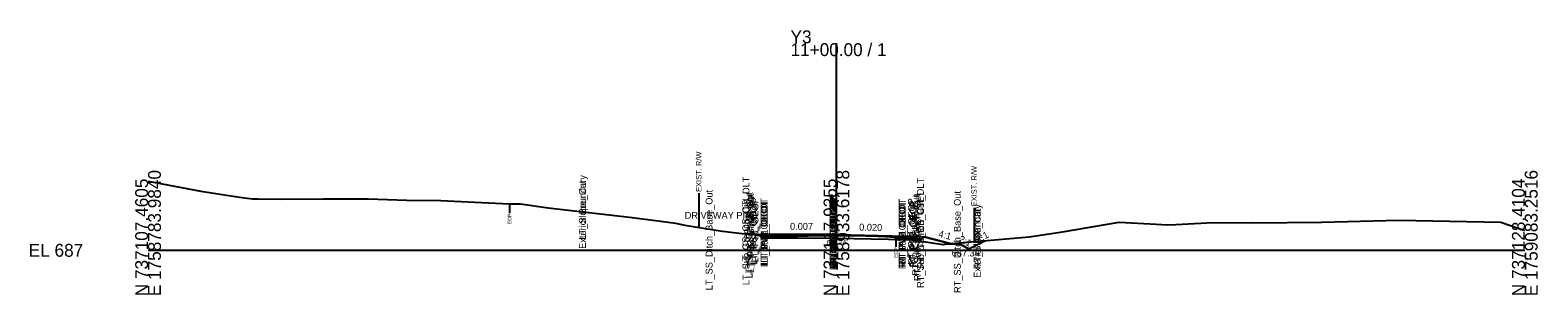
# Model space of a CAD drawing. Extents: x -26 to 1760432, y -10 to 737112.
# Drawn here: x -25.7 to 302.8, y 990.3 to 1047.9 of the extents above; entities that cross this region are included whole.
import ezdxf

# ---------------------------------------------------------------- set-up
doc = ezdxf.new("R2010")
doc.units = 0
for name, color, linetype in [('Default', 7, 'Continuous'), ('Exist Cross Section Cell', 7, 'Continuous'), ('Exist XS Center Line Elevation Label', 7, 'Continuous'), ('Exist XS Ground Line', 7, 'Continuous'), ('Old_Level_1', 7, 'Continuous'), ('Old_Level_10', 7, 'Continuous'), ('Prop CMT Pvmt Course 1', 7, 'Continuous'), ('Prop CMT Pvmt Course 2', 7, 'Continuous'), ('Prop CMT Pvmt Course 3', 7, 'Continuous'), ('Prop CMT Pvmt Surface', 7, 'Continuous'), ('Prop CMT Pvmt Surface Shoulder', 7, 'Continuous'), ('Prop CMT Pvmt Wedge Surface 1', 7, 'Continuous'), ('Prop CMT Shld Paved Course 1', 7, 'Continuous'), ('Prop CMT Shld Paved Course 2', 7, 'Continuous'), ('Prop CMT Shld Paved Course 3', 7, 'Continuous'), ('Prop CMT Slope Grass', 7, 'Continuous'), ('Prop CMT Subgrade Earthwork', 7, 'Continuous'), ('Prop XS DDE', 7, 'Continuous'), ('Prop XS Ditch Standard Text', 7, 'Continuous'), ('Prop XS Earthwork Shape', 7, 'Continuous'), ('Prop XS SE Text', 7, 'Continuous'), ('Prop XS Side Slope Text', 7, 'Continuous'), ('Scratch_Level_5', 7, 'Continuous'), ('Scratch_Level_7', 7, 'Continuous')]:
    doc.layers.add(name, color=color, linetype=linetype)

msp = doc.modelspace()

# ---------------------------------------------------------------- linework, layer by layer
at = {"layer": 'Exist Cross Section Cell'}
for p, q in [((150, 1000), (150, 1045.08)), ((0, 1000), (150, 1000)), ((150, 1000), (300, 1000))]:
    msp.add_line(p, q, dxfattribs=at)
at = {"layer": 'Exist XS Ground Line'}
msp.add_lwpolyline([(0, 1015.03), (11.53, 1012.84), (19.94, 1011.56), (22.79, 1011.22), (23.98, 1011.17), (29.02, 1011.13), (38.07, 1011.2), (40.86, 1011.2), (48.06, 1011.19), (56.28, 1010.93), (63.82, 1010.82), (66.7, 1010.69), (78.78, 1010.12), (81.18, 1010.12), (87.19, 1009.22), (96.07, 1008.24), (104.93, 1007.18), (111.18, 1006.39), (114.96, 1005.88), (116.94, 1005.49), (125.12, 1004.2), (125.86, 1004.11), (127.58, 1003.9), (130.08, 1003.59), (132.15, 1003.41), (132.59, 1003.37), (134.49, 1003.14), (135.1, 1003.08), (135.48, 1003.05), (136.03, 1003.02), (136.64, 1002.98), (136.95, 1002.99), (137.29, 1003.02), (137.6, 1003.03), (139.18, 1003.06), (140.11, 1003.07), (141.52, 1003.1), (142.61, 1003.12), (143.86, 1003.16), (145.12, 1003.2), (146.2, 1003.2), (147.63, 1003.21), (149.84, 1003.24), (152.64, 1003.21), (153.23, 1003.21), (155.14, 1003.2), (155.57, 1003.19), (157.91, 1003.15), (160.16, 1003.06), (160.72, 1003.01), (162.83, 1002.83), (173.27, 1001.28), (173.59, 1001.31), (191.99, 1002.92), (199.23, 1004.02), (211.62, 1006.09), (219.68, 1005.69), (222.07, 1005.56), (223.97, 1005.63), (232.09, 1006.03), (240.75, 1005.96), (255.74, 1006.11), (272.58, 1006.53), (294.8, 1006.1), (300, 1004.3)], dxfattribs=at)
at = {"layer": 'Old_Level_10'}
for p, q in [((120, 1012.41), (120, 1005.01)), ((78.78, 1010.12), (78.78, 1008.07)), ((180, 1009.27), (180, 1001.87)), ((162.94, 1002.81), (162.94, 1000.76))]:
    msp.add_line(p, q, dxfattribs=at)
at = {"layer": 'Prop CMT Pvmt Course 1'}
for points in [[(150, 1003.41), (135, 1003.51)], [(135, 1003.51), (135, 1003.26)], [(135, 1003.26), (150, 1003.16)], [(150, 1003.16), (150, 1003.41)], [(150, 1003.41), (165.09, 1003.11)], [(165.09, 1002.86), (162.94, 1002.9)], [(165.09, 1003.11), (165.09, 1002.86)]]:
    msp.add_lwpolyline(points, dxfattribs=at)
msp.add_lwpolyline([(150, 1003.16), (150, 1003.29), (150, 1003.29), (150, 1003.16)], close=True, dxfattribs=at)
at = {"layer": 'Prop CMT Pvmt Course 2'}
msp.add_line((137.6, 1003.04), (137.6, 1003.25), dxfattribs=at)
for points in [[(150, 1003.16), (135, 1003.26)], [(135, 1003.26), (135, 1003.05)], [(135, 1003.05), (137.6, 1003.04)], [(162.94, 1002.9), (165.09, 1002.86)], [(165.09, 1002.65), (162.94, 1002.7)], [(165.09, 1002.86), (165.09, 1002.65)]]:
    msp.add_lwpolyline(points, dxfattribs=at)
at = {"layer": 'Prop CMT Pvmt Course 3'}
msp.add_line((137.6, 1003.03), (137.6, 1003.04), dxfattribs=at)
for points in [[(137.6, 1003.04), (135, 1003.05)], [(135, 1003.05), (135, 1002.72)], [(135, 1002.72), (137.6, 1002.7)], [(162.94, 1002.7), (165.09, 1002.65)], [(165.09, 1002.32), (162.94, 1002.36)], [(165.09, 1002.65), (165.09, 1002.32)]]:
    msp.add_lwpolyline(points, dxfattribs=at)
at = {"layer": 'Prop CMT Pvmt Surface'}
for points in [[(150, 1003.41), (135, 1003.51)], [(150, 1003.41), (165.09, 1003.11)]]:
    msp.add_lwpolyline(points, dxfattribs=at)
at = {"layer": 'Prop CMT Pvmt Surface Shoulder'}
msp.add_lwpolyline([(165.09, 1003.11), (167.09, 1003.07)], dxfattribs=at)
at = {"layer": 'Prop CMT Pvmt Wedge Surface 1'}
for p, q in [((137.6, 1003.25), (137.6, 1003.37)), ((150, 1003.29), (137.6, 1003.37)), ((137.6, 1003.37), (137.6, 1003.25)), ((137.6, 1003.25), (144.92, 1003.2)), ((137.6, 1003.25), (137.6, 1003.04)), ((144.92, 1003.2), (137.6, 1003.25)), ((137.6, 1003.04), (137.6, 1003.03)), ((150, 1003.24), (150, 1003.29)), ((150, 1003.29), (150, 1003.24)), ((154.38, 1003.2), (150, 1003.29)), ((162.94, 1003.03), (158.99, 1003.11)), ((162.94, 1002.81), (162.94, 1003.03))]:
    msp.add_line(p, q, dxfattribs=at)
for points in [[(150, 1003.29), (137.6, 1003.37)], [(137.6, 1003.03), (139.18, 1003.06), (140.11, 1003.07), (141.52, 1003.1), (142.61, 1003.12), (143.86, 1003.16), (144.92, 1003.2)], [(144.92, 1003.2), (145.12, 1003.2), (146.2, 1003.2), (147.63, 1003.21), (149.84, 1003.24), (150, 1003.24)], [(150, 1003.29), (162.94, 1003.03)], [(150, 1003.24), (152.64, 1003.21), (153.23, 1003.21), (154.38, 1003.2)], [(158.99, 1003.11), (160.16, 1003.06), (160.72, 1003.01), (162.83, 1002.83), (162.94, 1002.81)], [(162.94, 1002.81), (162.94, 1002.9), (162.94, 1003.03)]]:
    msp.add_lwpolyline(points, dxfattribs=at)
at = {"layer": 'Prop CMT Shld Paved Course 1'}
for points in [[(135, 1003.51), (134.75, 1003.26)], [(134.75, 1003.26), (135, 1003.26)], [(135, 1003.26), (135, 1003.51)], [(165.09, 1003.11), (167.09, 1003.07), (167.34, 1002.82)], [(165.09, 1002.86), (165.09, 1003.11)], [(167.34, 1002.82), (165.09, 1002.86)]]:
    msp.add_lwpolyline(points, dxfattribs=at)
at = {"layer": 'Prop CMT Shld Paved Course 2'}
for points in [[(135, 1003.26), (134.75, 1003.26), (134.54, 1003.06)], [(134.54, 1003.06), (137, 1003.04)], [(135, 1003.05), (135, 1003.26)], [(165.09, 1002.86), (167.34, 1002.82), (167.55, 1002.6)], [(165.09, 1002.65), (165.09, 1002.86)], [(167.55, 1002.6), (165.09, 1002.65)]]:
    msp.add_lwpolyline(points, dxfattribs=at)
at = {"layer": 'Prop CMT Shld Paved Course 3'}
for points in [[(135, 1003.05), (134.54, 1003.06), (134.04, 1003.06), (133.71, 1002.73)], [(133.71, 1002.73), (135, 1002.72)], [(135, 1002.72), (135, 1003.05)], [(165.09, 1002.65), (167.55, 1002.6), (168.05, 1002.59), (168.39, 1002.25)], [(165.09, 1002.32), (165.09, 1002.65)], [(168.39, 1002.25), (165.09, 1002.32)]]:
    msp.add_lwpolyline(points, dxfattribs=at)
at = {"layer": 'Prop CMT Slope Grass'}
for points in [[(135, 1003.51), (132.48, 1003.38)], [(167.09, 1003.07), (169.09, 1002.91), (175, 1001.43)]]:
    msp.add_lwpolyline(points, dxfattribs=at)
at = {"layer": 'Prop CMT Subgrade Earthwork'}
for p, q in [((137.6, 1003.03), (137.6, 1002.7)), ((162.94, 1002.36), (162.94, 1002.81))]:
    msp.add_line(p, q, dxfattribs=at)
for points in [[(133.71, 1002.73), (133.04, 1003.41)], [(135, 1002.72), (133.71, 1002.73)], [(137.6, 1002.7), (135, 1002.72)], [(162.94, 1002.36), (165.09, 1002.32)], [(165.09, 1002.32), (168.39, 1002.25)], [(168.39, 1002.25), (169.05, 1002.91)]]:
    msp.add_lwpolyline(points, dxfattribs=at)
at = {"layer": 'Prop XS DDE'}
for p, q in [((178.86, 1000.34), (182.33, 1002.07)), ((177, 1001.27), (175, 1001.43)), ((178.86, 1000.34), (177, 1001.27))]:
    msp.add_line(p, q, dxfattribs=at)
at = {"layer": 'Prop XS Earthwork Shape'}
for points in [[(133.14, 1003.3), (133.04, 1003.41), (132.48, 1003.38), (132.59, 1003.37)], [(165.09, 1002.32), (166.47, 1002.29), (162.83, 1002.83), (160.72, 1003.01), (160.16, 1003.06), (157.91, 1003.15), (155.57, 1003.19), (155.14, 1003.2), (153.23, 1003.21), (152.64, 1003.21), (149.84, 1003.24), (147.63, 1003.21), (146.2, 1003.2), (145.12, 1003.2), (143.86, 1003.16), (142.61, 1003.12), (141.52, 1003.1), (140.11, 1003.07), (139.18, 1003.06), (137.6, 1003.03), (137.29, 1003.02), (136.95, 1002.99), (136.64, 1002.98), (136.03, 1003.02), (135.48, 1003.05), (135.1, 1003.08), (134.49, 1003.14), (133.14, 1003.3), (133.71, 1002.73), (135, 1002.72), (150, 1002.62)], [(166.47, 1002.29), (173.27, 1001.28), (173.59, 1001.31), (175, 1001.43), (169.09, 1002.91), (169.05, 1002.91), (168.39, 1002.25)]]:
    msp.add_lwpolyline(points, close=True, dxfattribs=at)
at = {"layer": 'Scratch_Level_5'}
for p, q in [((178.86, 1000.34), (182.33, 1002.07)), ((182.33, 1002.07), (180, 1001.87)), ((180, 1001.87), (175, 1001.43)), ((175, 1001.43), (177, 1001.27)), ((177, 1001.27), (178.86, 1000.34))]:
    msp.add_line(p, q, dxfattribs=at)

# ---------------------------------------------------------------- texts
at = {"layer": 'Default'}
msp.add_text('-', height=0.0001, dxfattribs=at).set_placement((0, 1000))
at = {"layer": 'Exist Cross Section Cell'}
for s, p in [('Y3', (140, 1045.08)), ('11+00.00 / 1', (140, 1042.28)), ('EL 687', (-26, 998.6))]:
    msp.add_text(s, height=2.8, dxfattribs=at).set_placement(p)
for s, p in [('N 737107.4605', (0, 990)), ('E 1758783.9840', (2.8, 990)), ('N 737117.9355', (150, 990)), ('E 1758933.6178', (152.8, 990)), ('N 737128.4104', (300, 990)), ('E 1759083.2516', (302.8, 990))]:
    msp.add_text(s, height=2.8, rotation=90, dxfattribs=at).set_placement(p)
at = {"layer": 'Exist XS Center Line Elevation Label'}
msp.add_text('690.24', height=1, dxfattribs=at).set_placement((147.86, 1001.24))
at = {"layer": 'Old_Level_1'}
msp.add_text('DRIVEWAY PIPE', height=1.5, dxfattribs=at).set_placement((116.94, 1006.86))
at = {"layer": 'Old_Level_10'}
for s, height, p in [('EXIST. R/W', 1.181, (120.59, 1012.71)), ('EXIST. R/W', 1.181, (180.59, 1009.57)), ('EOP', 0.787, (79.18, 1005.68)), ('EOP', 0.787, (163.33, 998.36))]:
    msp.add_text(s, height=height, rotation=90, dxfattribs=at).set_placement(p)
at = {"layer": 'Prop XS Ditch Standard Text'}
msp.add_text('687.34', height=1.5, dxfattribs=at).set_placement((175.11, 998.66))
at = {"layer": 'Prop XS SE Text'}
for s, rotation, p in [('0.007', 359.618, (139.88, 1004.48)), ('0.020', 358.8542, (154.94, 1004.31))]:
    msp.add_text(s, height=1.5, rotation=rotation, dxfattribs=at).set_placement(p)
at = {"layer": 'Prop XS Side Slope Text'}
for s, rotation, p in [('4:1', 345.9638, (172.11, 1002.93)), ('2:1', 333.4349, (176.5, 1001.98)), ('2:1', 26.5651, (180.85, 1001.65))]:
    msp.add_text(s, height=1.5, rotation=rotation, dxfattribs=at).set_placement(p)
at = {"layer": 'Scratch_Level_7'}
for s, p in [('Exterior Boundary', (95.41, 1000.31)), ('LT_Sub_Trench_Out_DLT', (131.04, 992.4)), ('RT_Sub_Trench_Out_DLT', (169.05, 991.8)), ('LT_Slope_Cut', (95.41, 1002.32)), ('LT_SS_Ditch_Base_Out', (123, 991.3)), ('LT_Sub_Trench_Out', (131.71, 993.91)), ('LT_PS3_Shelf_Out', (132.04, 995.06)), ('RT_PV1_OEEOP', (150, 996.47)), ('LT_PV1_OEEOP', (150, 996.56)), ('RT_PV2_OEEOP', (150, 996.16)), ('RT_PS3_Shelf_Out', (168.05, 994.49)), ('RT_Sub_Trench_Out', (168.39, 993.33)), ('RT_SS_Ditch_Base_Out', (177.09, 990.71)), ('LT_GS_OS_CTL', (131, 996.61)), ('LT_PS3_OEOP', (132.54, 996.75)), ('LT_PS2_OEOP', (132.75, 996.96)), ('LT_PS1_OEOP', (133, 997.39)), ('LT_Sub_OEOT', (135, 996.37)), ('LT_PV1_OEOT', (135, 997.31)), ('LT_PV2_OEOT', (135, 996.88)), ('LT_PV3_OEOT', (135, 996.67)), ('RT_Sub_OEEOP', (150, 995.66)), ('LT_Sub_OEEOP', (150, 995.75)), ('RT_PV1_IEEOP', (150, 997.04)), ('RT_PV3_OEEOP', (150, 995.95)), ('LT_PV2_OEEOP', (150, 996.25)), ('LT_PV1_IEEOP', (150, 997.13)), ('RT_PV2_IEEOP', (150, 996.73)), ('LT_PV3_OEEOP', (150, 996.04)), ('LT_PV2_IEEOP', (150, 996.82)), ('RT_Sub_OEOT', (165.09, 995.88)), ('RT_PV1_OEOT', (165.09, 996.82)), ('RT_PV2_OEOT', (165.09, 996.39)), ('RT_PV3_OEOT', (165.09, 996.18)), ('RT_PS1_OEOP', (167.09, 996.84)), ('RT_PS2_OEOP', (167.34, 996.41)), ('RT_PS3_OEOP', (167.55, 996.19)), ('RT_GS_OS_CTL', (169.09, 996.02)), ('Exterior Boundary', (181.42, 993.99)), ('RT_Slope_Cut', (181.42, 995.91)), ('PV1_PGL', (150, 999.62)), ('PV2_PGL', (150, 999.19))]:
    msp.add_text(s, height=1.5, rotation=90, dxfattribs=at).set_placement(p)

doc.saveas('drawing.dxf')
